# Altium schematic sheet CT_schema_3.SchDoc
size 298 x 230 mm
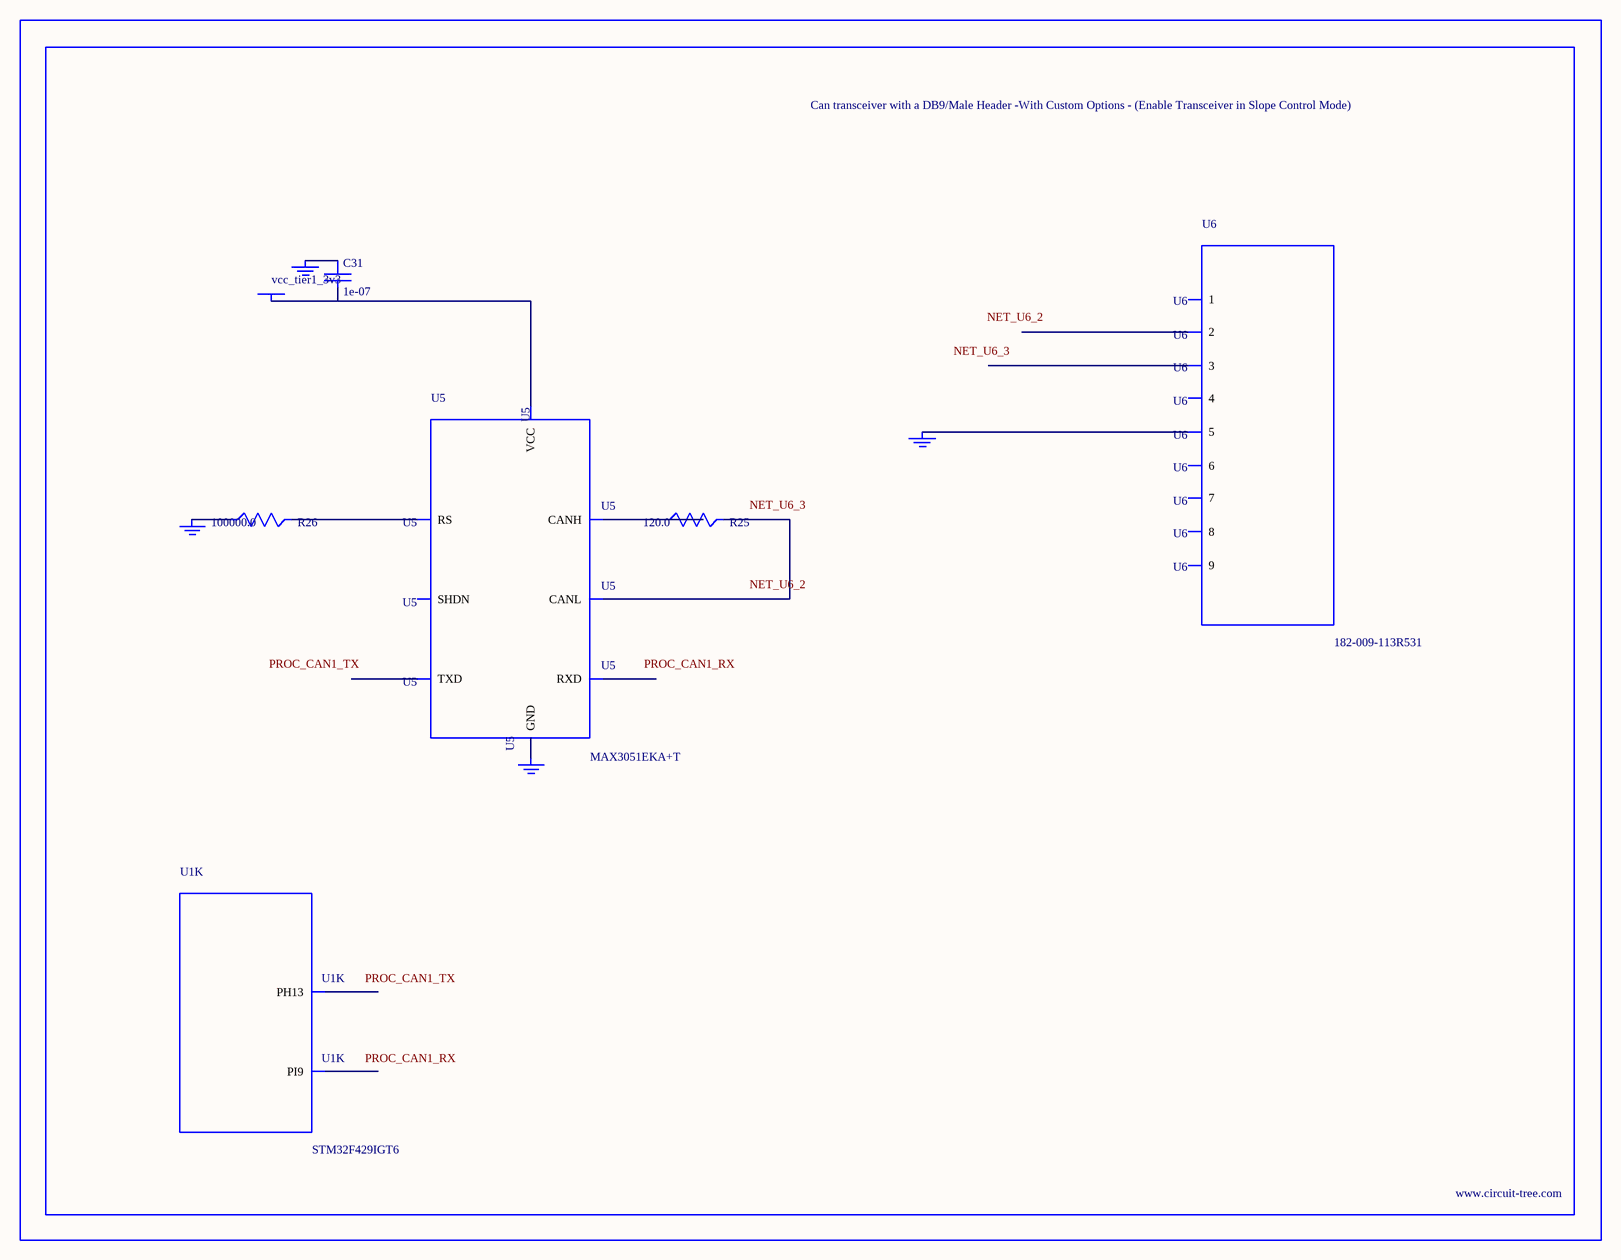
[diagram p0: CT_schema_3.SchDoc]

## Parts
BORDER2  (no value)
C31  1e-07  [C0402]
GND_INSTANCE_2_0  (no value)
GND_INSTANCE_2_1  (no value)
GND_INSTANCE_2_2  (no value)
GND_INSTANCE_2_3  (no value)
POWER_INSTANCE_2_0  vcc_tier1_3v3
R25  120.0  [R0603]
R26  100000.0  [R0603]
U1  STM32F429IGT6  [LQFP176]  (part K of 15)
U5  MAX3051EKA+T  [SOT-23-8]
U6  182-009-113R531  [182-009-MALE]

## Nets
NetC31_1: C31.1 GND_INSTANCE_2_0.0(GND)
NetC31_2: C31.2 POWER_INSTANCE_2_0.0(PWR) U5.3(VCC)
NetGND_INSTANCE_2_1_0: GND_INSTANCE_2_1.0(GND) R26.1
NetGND_INSTANCE_2_2_0: GND_INSTANCE_2_2.0(GND) U5.2(GND)
NetGND_INSTANCE_2_3_0: GND_INSTANCE_2_3.0(GND) U6.5
NetR25_1: R25.1 U5.7(CANH)
NetR25_2: R25.2 U5.6(CANL)
NetR26_2: R26.2 U5.8(RS)

Not connected (* = marked no-connect by the designer): U1 11(PI9) 128(PH13); U5 1(TXD) 4(RXD) 5(SHDN); U6 1 2 3 4 6 7 8 9

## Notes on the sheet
- Labels drawn without touching a wire or pin: NET_U6_2, NET_U6_3, PROC_CAN1_RX, PROC_CAN1_TX

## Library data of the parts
BORDER2 = BORDER_PAGE2
C31 = C0402C104K3RACTU
GND_INSTANCE_2_0-GND_INSTANCE_2_3 = GND
POWER_INSTANCE_2_0 = PWR
R25 = RC0603JR-07120RL
R26 = RC0603JR-07100KL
